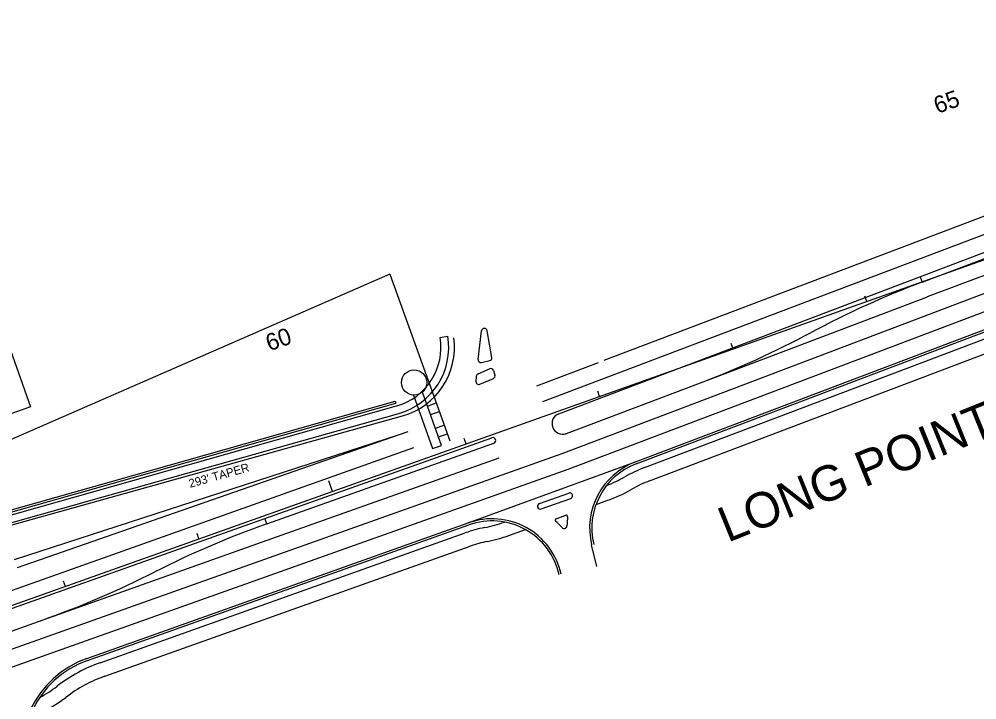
# Model space of a CAD drawing. Extents: x 2338610 to 2351914, y 366540 to 376484.
# Drawn here: x 2350110 to 2350785, y 368287 to 368767 of the extents above; entities that cross this region are included whole.
import ezdxf

# ---------------------------------------------------------------- set-up
doc = ezdxf.new("R2010")
doc.units = 0
for name, color, linetype in [('RD_HC_Cl', 7, 'Continuous'), ('RD_PD_ConcMed', 7, 'Continuous'), ('RD_PD_Final_LnLine', 7, 'Continuous'), ('RD_PD_Final_TrvlWay', 7, 'Continuous'), ('RD_PD_FOC', 7, 'Continuous'), ('RD_PD_NOISE-WALL-GM', 7, 'Continuous'), ('RD_PD_SW', 7, 'Continuous'), ('TR SN EXTRUDED PANEL SIGNS- MOUNTED OVERHEAD', 7, 'Continuous'), ('TR SN UNASSIGNED 4', 7, 'Continuous'), ('TR SN UNASSIGNED 7', 7, 'Continuous')]:
    doc.layers.add(name, color=color, linetype=linetype)

msp = doc.modelspace()

# ---------------------------------------------------------------- linework, layer by layer
at = {"layer": 'RD_HC_Cl'}
msp.add_line((2350026.96, 368325.73), (2350990.33, 368668.55), dxfattribs=at)
at = {"layer": 'RD_PD_ConcMed'}
for p, q in [((2350745.27, 368585.41), (2350746.69, 368581.67)), ((2350433.58, 368527.01), (2350435.96, 368547.18)), ((2350443.28, 368528.49), (2350439.91, 368547.3)), ((2350436.03, 368524.83), (2350441.77, 368526.19)), ((2350432.27, 368515.19), (2350432.04, 368511.5)), ((2350433.47, 368516.9), (2350441.62, 368520.42)), ((2350444.31, 368519.23), (2350445.39, 368516.06)), ((2350434.82, 368509.53), (2350444.28, 368513.57)), ((2350284.45, 368411), (2350283.11, 368414.76))]:
    msp.add_line(p, q, dxfattribs=at)
for centre, start, end in [((2350437.95, 368546.95), 10.1289, 173.26408), ((2350441.31, 368528.14), 283.35584, 10.1289), ((2350435.56, 368526.78), 173.26408, 283.35584), ((2350434.27, 368515.06), 113.39418, 176.37352), ((2350442.41, 368518.59), 18.8959, 113.39418), ((2350443.5, 368515.41), 293.08849, 18.8959), ((2350434.03, 368511.37), 176.37352, 293.08849)]:
    msp.add_arc(centre, 2, start, end, dxfattribs=at)
at = {"layer": 'RD_PD_Final_LnLine'}
for p, q in [((2350522.45, 368526.52), (2350987.15, 368702.86)), ((2350479.23, 368497.29), (2350991.4, 368691.65)), ((2350490.5, 368488.73), (2350995.66, 368680.43)), ((2350746.69, 368581.67), (2350997.08, 368676.69)), ((2350750.6, 368571.39), (2351000.98, 368666.4)), ((2350492.88, 368460.75), (2351005.24, 368655.18)), ((2350497.02, 368449.49), (2351009.5, 368643.96)), ((2350590.4, 368510.59), (2350750.54, 368571.36)), ((2350474.98, 368508.51), (2350518.4, 368524.98)), ((2350495.82, 368474.7), (2350590.4, 368510.59)), ((2350378.1, 368474.04), (2350384.24, 368476.22)), ((2350058.41, 368334.8), (2350443.27, 368471.76)), ((2350284.45, 368411), (2350444.62, 368467.99)), ((2350023.6, 368335.16), (2350388.26, 368464.92)), ((2350036.68, 368298.41), (2350492.88, 368460.75)), ((2350288.14, 368400.63), (2350448.3, 368457.63)), ((2350040.7, 368287.11), (2350497.02, 368449.49)), ((2350126.71, 368343.19), (2350288.14, 368400.63)), ((2350063.44, 368320.67), (2350126.71, 368343.19))]:
    msp.add_line(p, q, dxfattribs=at)
for centre, radius, start, end in [((2350984.41, 367955.26), 670, 110.78079, 118.12726), ((2350352.69, 369137.01), 670, 290.78079, 298.12726), ((2350493.16, 368481.72), 7.5, 110.78079, 200.78079), ((2350493.16, 368481.72), 7.5, 200.78079, 290.78079), ((2350443.93, 368469.87), 2, 289.58772, 109.14219), ((2350509.07, 367779.77), 670, 109.58804, 116.93451), ((2349902.09, 368974.41), 670, 289.58804, 296.93451)]:
    msp.add_arc(centre, radius, start, end, dxfattribs=at)
at = {"layer": 'RD_PD_Final_TrvlWay'}
for p, q in [((2350544.45, 368454.65), (2351013.75, 368632.74)), ((2350098.11, 368408.37), (2350380.3, 368487.28)), ((2350106.54, 368385.9), (2350378.1, 368474.04)), ((2350108.55, 368380.24), (2350378.1, 368474.04)), ((2350476.73, 368425.28), (2350497.49, 368432.67)), ((2350478.07, 368421.52), (2350498.83, 368428.9)), ((2350488.54, 368414.63), (2350495.36, 368417.05)), ((2350157.62, 368315.98), (2350426.54, 368411.67)), ((2350517.3, 368380.9), (2350513.61, 368396.08))]:
    msp.add_line(p, q, dxfattribs=at)
for centre, radius, start, end in [((2350366.84, 368535.44), 50, 285.62317, 8.00142), ((2350562.19, 368407.91), 50, 110.78079, 193.67822), ((2350498.16, 368430.79), 2, 289.58804, 109.58804), ((2350477.4, 368423.4), 2, 109.58804, 289.58804), ((2350443.3, 368364.56), 50, 12.44954, 109.58804), ((2350488.87, 368413.68), 1, 109.58804, 227.14864), ((2350495.7, 368416.11), 1, 352.96368, 109.58804), ((2350562.19, 368407.91), 66, 172.96368, 178.53457), ((2350443.3, 368364.56), 66, 41.52414, 47.14864), ((2350494.21, 368409.64), 2, 221.52414, 358.53457), ((2350181.09, 368250.03), 70, 109.58804, 199.58804)]:
    msp.add_arc(centre, radius, start, end, dxfattribs=at)
at = {"layer": 'RD_PD_FOC'}
for p, q in [((2350544.98, 368453.25), (2351014.29, 368631.34)), ((2350098.03, 368409.94), (2350377.52, 368488.89)), ((2350158.12, 368314.56), (2350427.04, 368410.26))]:
    msp.add_line(p, q, dxfattribs=at)
for centre, radius, start, end in [((2350364.33, 368535.56), 48.5, 285.77396, 9.46906), ((2350562.19, 368407.91), 48.5, 110.78079, 193.67822), ((2350443.3, 368364.56), 48.5, 12.44954, 109.58804), ((2350181.09, 368250.03), 68.5, 109.58804, 199.58804)]:
    msp.add_arc(centre, radius, start, end, dxfattribs=at)
at = {"layer": 'RD_PD_NOISE-WALL-GM'}
for p, q in [((2350094.92, 368418.38), (2350375.07, 368497.55)), ((2350095.38, 368416.95), (2350375.48, 368496.1)), ((2350375.07, 368497.55), (2350375.48, 368496.1))]:
    msp.add_line(p, q, dxfattribs=at)
at = {"layer": 'RD_PD_SW'}
for p, q in [((2350550.98, 368450.71), (2351015.88, 368627.13)), ((2350554.53, 368441.36), (2351019.43, 368617.78)), ((2350406.75, 368542.63), (2350412.17, 368543.54)), ((2350095.99, 368415.05), (2350376.02, 368494.18)), ((2350426.54, 368411.67), (2350544.45, 368454.65)), ((2350516.74, 368424.66), (2350524.36, 368427.37)), ((2350455.11, 368402.73), (2350466.91, 368406.93)), ((2350166.99, 368312.94), (2350424.5, 368404.58)), ((2350170.34, 368303.52), (2350427.86, 368395.16))]:
    msp.add_line(p, q, dxfattribs=at)
for centre, radius, start, end in [((2350364.33, 368535.56), 43, 285.77396, 9.46906), ((2350586.46, 368357.22), 100, 110.78079, 119.66427), ((2350487.48, 368531.01), 100, 291.50106, 299.66427), ((2350586.46, 368357.22), 90, 110.78079, 119.66427), ((2350487.48, 368531.01), 110, 289.58804, 299.66427), ((2350458.03, 368310.36), 100, 101.47842, 109.58804), ((2350418.23, 368506.36), 100, 281.47842, 289.78076), ((2350418.23, 368506.36), 110, 281.47842, 289.58804), ((2350458.03, 368310.36), 90, 101.47842, 109.58804), ((2350203.87, 368209.31), 110, 109.58804, 127.67194), ((2350203.87, 368209.31), 100, 109.58804, 127.67194), ((2350081.64, 368367.61), 90, 298.31725, 307.67194), ((2350081.64, 368367.61), 100, 290.66898, 307.67194)]:
    msp.add_arc(centre, radius, start, end, dxfattribs=at)
at = {"layer": 'TR SN EXTRUDED PANEL SIGNS- MOUNTED OVERHEAD'}
for p, q in [((2350371.33, 368587.27), (2350018.12, 368432.95)), ((2350371.33, 368587.27), (2350402.29, 368501.11)), ((2350397.77, 368494.13), (2350404.02, 368496.38)), ((2350402.29, 368501.11), (2350407.94, 368485.4)), ((2350399.94, 368488.08), (2350406.22, 368490.34)), ((2350407.94, 368485.4), (2350413.58, 368469.69)), ((2350403.42, 368478.42), (2350409.67, 368480.67)), ((2350405.59, 368472.37), (2350411.87, 368474.63))]:
    msp.add_line(p, q, dxfattribs=at)
msp.add_lwpolyline([(2350065.43, 368475.02), (2349954.12, 368789.94), (2350006.6, 368808.49), (2350117.9, 368493.56)], close=True, dxfattribs=at)
msp.add_lwpolyline([(2350387.86, 368501.89), (2350401.44, 368464.12), (2350407.74, 368466.38), (2350394.21, 368504.04)], dxfattribs=at)
msp.add_circle((2350388.38, 368510.78), 8.91, dxfattribs=at)
at = {"layer": 'TR SN UNASSIGNED 7'}
for p, q in [((2350707.69, 368567.97), (2350706.35, 368571.74)), ((2350613.48, 368534.45), (2350612.14, 368538.22)), ((2350519.27, 368500.92), (2350517.92, 368504.69)), ((2350425.05, 368467.4), (2350423.71, 368471.17)), ((2350330.84, 368433.87), (2350328.16, 368441.41)), ((2350236.63, 368400.35), (2350235.29, 368404.11)), ((2350142.41, 368366.82), (2350141.07, 368370.59))]:
    msp.add_line(p, q, dxfattribs=at)

# ---------------------------------------------------------------- texts
at = {"layer": 'RD_PD_Final_TrvlWay'}
msp.add_text("293' TAPER", height=6, rotation=15.62317, dxfattribs=at).set_placement((2350230.38, 368436.38))
at = {"layer": 'TR SN UNASSIGNED 4'}
msp.add_text('LONG POINT ROAD', height=25, rotation=22.01754, dxfattribs=at).set_placement((2350609.5, 368397.51))
at = {"layer": 'TR SN UNASSIGNED 7'}
for s, p in [('65', (2350757.48, 368700.32)), ('60', (2350286.29, 368532.65))]:
    msp.add_text(s, height=12, rotation=19.58804, dxfattribs=at).set_placement(p)

doc.saveas('drawing.dxf')
